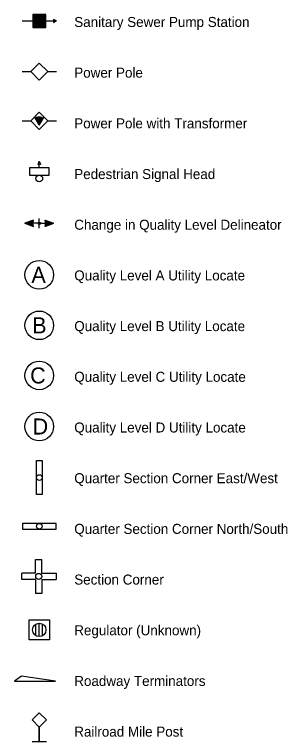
# Model space of a CAD drawing. Extents: x -371 to 730, y -9 to 425.
# Drawn here: x -247.7 to -200.1, y 165.8 to 292.7 of the extents above; entities that cross this region are included whole.
import ezdxf

# ---------------------------------------------------------------- set-up
doc = ezdxf.new("R2010")
doc.units = 0
for name, color, linetype in [('GasReg_ep', 7, 'Continuous'), ('GovQuarterLine_ep', 7, 'Continuous'), ('GovSectionLine_ep', 7, 'Continuous'), ('PedSignal_ep', 7, 'Continuous'), ('PolePower_ep', 7, 'Continuous'), ('RailroadMisc_ep', 7, 'Continuous'), ('SanitaryMisc_ep', 7, 'Continuous'), ('SU_Misc_ep', 7, 'Continuous'), ('SU_QLA_ep', 7, 'Continuous'), ('SU_QLB_ep', 7, 'Continuous'), ('SU_QLC_ep', 7, 'Continuous'), ('SU_QLD_ep', 7, 'Continuous')]:
    doc.layers.add(name, color=color, linetype=linetype)

# ---------------------------------------------------------------- blocks, each defined once
blk = doc.blocks.new('QDEL')
at = {"layer": 'SU_Misc_ep'}
for p, q in [((-1, 0.56), (-2.5, 0)), ((-2.49, 0), (-2.49, 0.01)), ((-2.47, -0.01), (-2.44, 0.02)), ((-2.45, -0.02), (-2.39, 0.04)), ((-2.43, -0.03), (-2.34, 0.06)), ((-2.4, -0.04), (-2.29, 0.08)), ((-2.38, -0.04), (-2.24, 0.1)), ((-2.36, -0.05), (-2.19, 0.12)), ((-2.34, -0.06), (-2.14, 0.13)), ((-2.31, -0.07), (-2.09, 0.15)), ((-2.29, -0.08), (-2.04, 0.17)), ((-2.27, -0.09), (-1.99, 0.19)), ((-2.25, -0.09), (-1.94, 0.21)), ((-2.22, -0.1), (-1.89, 0.23)), ((-2.2, -0.11), (-1.84, 0.25)), ((-2.18, -0.12), (-1.79, 0.26)), ((-2.16, -0.13), (-1.74, 0.28)), ((-2.13, -0.14), (-1.7, 0.3)), ((-2.11, -0.15), (-1.65, 0.32)), ((-2.09, -0.15), (-1.6, 0.34)), ((-2.07, -0.16), (-1.55, 0.36)), ((-2.04, -0.17), (-1.5, 0.37)), ((-2.02, -0.18), (-1.45, 0.39)), ((-2, -0.19), (-1.4, 0.41)), ((-1.98, -0.2), (-1.35, 0.43)), ((-1.95, -0.2), (-1.3, 0.45)), ((-1.93, -0.21), (-1.25, 0.47)), ((-1.91, -0.22), (-1.2, 0.49)), ((-1.89, -0.23), (-1.15, 0.5)), ((-1.86, -0.24), (-1.1, 0.52)), ((-1.84, -0.25), (-1.05, 0.54)), ((-1.82, -0.25), (-1, 0.56)), ((-1.8, -0.26), (-1.01, 0.52)), ((-1.77, -0.27), (-1.02, 0.48)), ((-1.75, -0.28), (-1.03, 0.44)), ((-1.73, -0.29), (-1.04, 0.4)), ((-1.71, -0.3), (-1.05, 0.35)), ((-1.68, -0.31), (-1.07, 0.31)), ((-1.66, -0.31), (-1.08, 0.27)), ((-1.64, -0.32), (-1.09, 0.23)), ((-1.62, -0.33), (-1.1, 0.19)), ((-1.59, -0.34), (-1.11, 0.15)), ((-1.57, -0.35), (-1.12, 0.11)), ((-1.55, -0.36), (-1.13, 0.06)), ((-1.53, -0.36), (-1.14, 0.02)), ((-1.14, 0), (-1, 0.56)), ((0, 0), (0, 0.83)), ((1.14, 0), (1, 0.56)), ((1, 0.56), (2.5, 0)), ((1, 0.56), (1, 0.56)), ((1, -0.56), (1.81, 0.26)), ((1.01, 0.53), (1.03, 0.55)), ((1.01, -0.51), (1.79, 0.26)), ((1.02, 0.51), (1.05, 0.54)), ((1.02, 0.48), (1.07, 0.53)), ((1.02, -0.47), (1.77, 0.27)), ((1.03, 0.46), (1.09, 0.53)), ((1.03, 0.43), (1.12, 0.52)), ((1.03, -0.43), (1.75, 0.28)), ((1.04, 0.41), (1.14, 0.51)), ((1.05, 0.39), (1.16, 0.5)), ((1.05, 0.36), (1.18, 0.49)), ((1.05, -0.39), (1.72, 0.29)), ((1.05, -0.54), (1.84, 0.25)), ((1.06, 0.34), (1.21, 0.48)), ((1.06, -0.35), (1.7, 0.3)), ((1.07, 0.31), (1.23, 0.48)), ((1.07, 0.29), (1.25, 0.47)), ((1.07, -0.31), (1.68, 0.31)), ((1.08, 0.26), (1.27, 0.46)), ((1.08, 0.24), (1.3, 0.45)), ((1.08, -0.26), (1.66, 0.32)), ((1.09, 0.21), (1.32, 0.44)), ((1.09, -0.22), (1.63, 0.32)), ((1.09, -0.53), (1.86, 0.24)), ((1.1, 0.19), (1.34, 0.43)), ((1.1, 0.16), (1.36, 0.42)), ((1.1, -0.18), (1.61, 0.33)), ((1.11, 0.14), (1.39, 0.42)), ((1.11, -0.14), (1.59, 0.34)), ((1.12, 0.11), (1.41, 0.41)), ((1.12, 0.09), (1.43, 0.4)), ((1.12, -0.1), (1.57, 0.35)), ((1.13, 0.06), (1.45, 0.39)), ((1.13, 0.04), (1.48, 0.38)), ((1.13, -0.06), (1.54, 0.36)), ((1.14, -0.02), (1.52, 0.37)), ((1.14, 0.02), (1.5, 0.37)), ((1.14, -0.51), (1.88, 0.23)), ((1.19, -0.49), (1.9, 0.22)), ((1.24, -0.47), (1.93, 0.21)), ((1.29, -0.45), (1.95, 0.21)), ((1.34, -0.43), (1.97, 0.2)), ((1.39, -0.41), (1.99, 0.19)), ((1.44, -0.4), (2.02, 0.18)), ((1.49, -0.38), (2.04, 0.17)), ((1.54, -0.36), (2.06, 0.16)), ((1.59, -0.34), (2.08, 0.16)), ((1.64, -0.32), (2.11, 0.15)), ((1.69, -0.3), (2.13, 0.14)), ((1.74, -0.29), (2.15, 0.13)), ((1.79, -0.27), (2.17, 0.12)), ((1.84, -0.25), (2.2, 0.11)), ((1.89, -0.23), (2.22, 0.1)), ((1.93, -0.21), (2.24, 0.1)), ((1.98, -0.19), (2.27, 0.09)), ((2.03, -0.17), (2.29, 0.08)), ((2.08, -0.16), (2.31, 0.07)), ((2.13, -0.14), (2.33, 0.06)), ((2.18, -0.12), (2.36, 0.05)), ((2.23, -0.1), (2.38, 0.05)), ((2.28, -0.08), (2.4, 0.04)), ((2.33, -0.06), (2.42, 0.03)), ((2.38, -0.05), (2.45, 0.02)), ((2.43, -0.03), (2.47, 0.01)), ((2.48, -0.01), (2.49, 0)), ((0, 0), (-2.5, 0)), ((-2.5, 0), (-1, -0.56)), ((-1.5, -0.37), (-1.14, -0.01)), ((-1.48, -0.38), (-1.14, -0.04)), ((-1.46, -0.39), (-1.13, -0.06)), ((-1.44, -0.4), (-1.12, -0.09)), ((-1.41, -0.41), (-1.12, -0.11)), ((-1.39, -0.41), (-1.11, -0.13)), ((-1.37, -0.42), (-1.1, -0.16)), ((-1.35, -0.43), (-1.1, -0.18)), ((-1.32, -0.44), (-1.09, -0.21)), ((-1.3, -0.45), (-1.09, -0.23)), ((-1.28, -0.46), (-1.08, -0.26)), ((-1.26, -0.47), (-1.07, -0.28)), ((-1.23, -0.47), (-1.07, -0.31)), ((-1.21, -0.48), (-1.06, -0.33)), ((-1.19, -0.49), (-1.05, -0.36)), ((-1.17, -0.5), (-1.05, -0.38)), ((-1, -0.56), (-1.14, 0)), ((-1.14, -0.51), (-1.04, -0.41)), ((-1.12, -0.52), (-1.04, -0.43)), ((-1.1, -0.52), (-1.03, -0.46)), ((-1.08, -0.53), (-1.02, -0.48)), ((-1.05, -0.54), (-1.02, -0.5)), ((-1.03, -0.55), (-1.01, -0.53)), ((-1.01, -0.56), (-1, -0.55)), ((0, -0.83), (0, 0)), ((0, 0), (2.5, 0)), ((2.5, 0), (1, -0.56)), ((1, -0.56), (1.14, 0))]:
    blk.add_line(p, q, dxfattribs=at)
blk.add_circle((0, 0), 0.2, dxfattribs=at)
blk = doc.blocks.new('QLA')
at = {"layer": 'SU_QLA_ep'}
blk.add_circle((0, 0), 2.5, dxfattribs=at)
blk.add_text('A', height=2.8, dxfattribs=at).set_placement((-1.37, -1.4))
blk = doc.blocks.new('QLB')
at = {"layer": 'SU_QLB_ep'}
blk.add_circle((0, 0), 2.5, dxfattribs=at)
blk.add_text('B', height=2.8, dxfattribs=at).set_placement((-1.23, -1.4))
blk = doc.blocks.new('QLC')
at = {"layer": 'SU_QLC_ep'}
blk.add_circle((0, 0), 2.5, dxfattribs=at)
blk.add_text('C', height=2.8, dxfattribs=at).set_placement((-1.59, -1.4))
blk = doc.blocks.new('QLD')
at = {"layer": 'SU_QLD_ep'}
blk.add_circle((0, 0), 2.5, dxfattribs=at)
blk.add_text('D', height=2.8, dxfattribs=at).set_placement((-1.15, -1.4))
blk = doc.blocks.new('roadway_terminators_ArrTermLoc')
blk.add_lwpolyline([(0, 0), (-0.989, 0.148), (-1.187, 0)], close=True)

msp = doc.modelspace()

# ---------------------------------------------------------------- linework, layer by layer
at = {"layer": 'GasReg_ep'}
for p, q in [((-243.95, 184.36), (-243.95, 186.12)), ((-243.37, 184.18), (-243.37, 186.28)), ((-242.78, 184.37), (-242.78, 186.14))]:
    msp.add_line(p, q, dxfattribs=at)
msp.add_lwpolyline([(-241.61, 187), (-241.61, 183.5), (-245.11, 183.5), (-245.11, 187), (-241.61, 187)], dxfattribs=at)
msp.add_circle((-243.37, 185.26), 1.17, dxfattribs=at)
at = {"layer": 'GovQuarterLine_ep'}
for points in [[(-243.86, 208.89), (-243.86, 214.81), (-242.87, 214.81), (-242.87, 208.89)], [(-246.32, 203.83), (-246.32, 202.85), (-240.41, 202.85), (-240.41, 203.83)]]:
    msp.add_lwpolyline(points, close=True, dxfattribs=at)
for centre in [(-243.37, 211.85), (-243.37, 203.34)]:
    msp.add_circle(centre, 0.493, dxfattribs=at)
at = {"layer": 'GovSectionLine_ep'}
for p, q in [((-244, 195.14), (-244, 197.55)), ((-244, 197.55), (-242.95, 197.55)), ((-242.95, 195.14), (-242.95, 197.55)), ((-246.42, 194.07), (-246.42, 195.14)), ((-244, 195.14), (-246.42, 195.14)), ((-242.95, 195.14), (-240.44, 195.14)), ((-240.44, 195.14), (-240.44, 194.07)), ((-244, 194.07), (-246.42, 194.07)), ((-244, 194.07), (-244, 191.64)), ((-242.95, 194.07), (-240.44, 194.07)), ((-242.95, 194.07), (-242.95, 191.64)), ((-242.95, 191.64), (-244, 191.64))]:
    msp.add_line(p, q, dxfattribs=at)
msp.add_circle((-243.47, 194.6), 0.527, dxfattribs=at)
at = {"layer": 'PedSignal_ep'}
msp.add_lwpolyline([(-243.37, 265.91), (-243.37, 266.49), (-243.58, 266.49), (-243.37, 267.07), (-243.15, 266.49), (-243.37, 266.49)], dxfattribs=at)
msp.add_lwpolyline([(-245.1, 264.65), (-241.63, 264.65), (-241.63, 265.91), (-245.1, 265.91)], close=True, dxfattribs=at)
msp.add_circle((-243.37, 264.07), 0.58, dxfattribs=at)
at = {"layer": 'PolePower_ep'}
for p, q in [((-246.37, 282.73), (-244.87, 282.73)), ((-246.37, 282.73), (-244.87, 282.73)), ((-246.37, 282.73), (-244.87, 282.73)), ((-241.87, 282.73), (-240.37, 282.73)), ((-241.87, 282.73), (-240.37, 282.73)), ((-241.87, 282.73), (-240.37, 282.73)), ((-246.37, 274.14), (-244.87, 274.14)), ((-243.37, 273.38), (-244.19, 274.81)), ((-243.37, 273.38), (-244.19, 274.81)), ((-243.37, 273.38), (-244.19, 274.81)), ((-243.37, 273.38), (-244.19, 274.81)), ((-243.37, 273.38), (-243.98, 274.75)), ((-243.37, 273.38), (-243.98, 274.75)), ((-243.37, 273.38), (-243.98, 274.75)), ((-243.37, 273.38), (-243.98, 274.75)), ((-243.37, 273.38), (-243.83, 274.81)), ((-243.37, 273.38), (-243.83, 274.81)), ((-243.37, 273.38), (-243.83, 274.81)), ((-243.37, 273.38), (-243.83, 274.81)), ((-243.37, 273.38), (-243.68, 274.85)), ((-243.37, 273.38), (-243.68, 274.85)), ((-243.37, 273.38), (-243.68, 274.85)), ((-243.37, 273.38), (-243.68, 274.85)), ((-243.37, 273.38), (-243.52, 274.87)), ((-243.37, 273.38), (-243.52, 274.87)), ((-243.37, 273.38), (-243.52, 274.87)), ((-243.37, 273.38), (-243.52, 274.87)), ((-243.37, 273.38), (-243.37, 274.88)), ((-243.37, 273.38), (-243.37, 274.88)), ((-243.37, 273.38), (-243.37, 274.88)), ((-243.37, 273.38), (-243.37, 274.88)), ((-243.37, 273.38), (-243.21, 274.87)), ((-243.37, 273.38), (-243.21, 274.87)), ((-243.37, 273.38), (-243.21, 274.87)), ((-243.37, 273.38), (-243.21, 274.87)), ((-243.37, 273.38), (-243.05, 274.85)), ((-243.37, 273.38), (-243.05, 274.85)), ((-243.37, 273.38), (-243.05, 274.85)), ((-243.37, 273.38), (-243.05, 274.85)), ((-243.37, 273.38), (-242.54, 274.81)), ((-243.37, 273.38), (-242.9, 274.81)), ((-243.37, 273.38), (-242.54, 274.81)), ((-243.37, 273.38), (-242.9, 274.81)), ((-243.37, 273.38), (-242.54, 274.81)), ((-243.37, 273.38), (-242.9, 274.81)), ((-243.37, 273.38), (-242.54, 274.81)), ((-243.37, 273.38), (-242.9, 274.81)), ((-243.37, 273.38), (-242.75, 274.75)), ((-243.37, 273.38), (-242.75, 274.75)), ((-243.37, 273.38), (-242.75, 274.75)), ((-243.37, 273.38), (-242.75, 274.75)), ((-241.87, 274.14), (-240.37, 274.14))]:
    msp.add_line(p, q, dxfattribs=at)
for points in [[(-244.87, 282.73), (-243.37, 281.23), (-241.87, 282.73), (-243.37, 284.23)], [(-244.87, 282.73), (-243.37, 281.23), (-241.87, 282.73), (-243.37, 284.23)], [(-244.87, 282.73), (-243.37, 281.23), (-241.87, 282.73), (-243.37, 284.23)], [(-244.87, 274.14), (-243.37, 272.64), (-241.87, 274.14), (-243.37, 275.64)]]:
    msp.add_lwpolyline(points, close=True, dxfattribs=at)
at = {"layer": 'RailroadMisc_ep'}
msp.add_lwpolyline([(-244.62, 165.78), (-243.37, 165.78), (-243.37, 168.28), (-244.62, 169.53), (-243.37, 170.78), (-242.12, 169.53), (-243.37, 168.28), (-243.37, 165.78), (-242.12, 165.78)], dxfattribs=at)
at = {"layer": 'SanitaryMisc_ep'}
for p, q in [((-244.49, 292.63), (-242.24, 292.63)), ((-244.49, 292.57), (-242.24, 292.57)), ((-244.49, 292.51), (-242.24, 292.51)), ((-244.49, 292.44), (-242.24, 292.44)), ((-244.49, 292.38), (-242.24, 292.38)), ((-244.49, 292.32), (-242.24, 292.32)), ((-244.49, 292.26), (-242.24, 292.26)), ((-244.49, 292.19), (-242.24, 292.19)), ((-244.49, 292.13), (-242.24, 292.13)), ((-244.49, 292.07), (-242.24, 292.07)), ((-244.49, 292.01), (-242.24, 292.01)), ((-244.49, 291.94), (-242.24, 291.94)), ((-246.37, 291.57), (-240.37, 291.57)), ((-244.49, 291.88), (-242.24, 291.88)), ((-244.49, 291.82), (-242.24, 291.82)), ((-244.49, 291.76), (-242.24, 291.76)), ((-244.49, 291.69), (-242.24, 291.69)), ((-244.49, 291.63), (-242.24, 291.63)), ((-244.49, 291.57), (-242.24, 291.57)), ((-244.49, 291.51), (-242.24, 291.51)), ((-244.49, 291.44), (-242.24, 291.44)), ((-244.49, 291.38), (-242.24, 291.38)), ((-244.49, 291.32), (-242.24, 291.32)), ((-244.49, 291.26), (-242.24, 291.26)), ((-244.49, 291.19), (-242.24, 291.19)), ((-244.49, 291.13), (-242.24, 291.13)), ((-244.49, 291.07), (-242.24, 291.07)), ((-244.49, 291.01), (-242.24, 291.01)), ((-244.49, 290.94), (-242.24, 290.94)), ((-244.49, 290.88), (-242.24, 290.88)), ((-244.49, 290.82), (-242.24, 290.82)), ((-244.49, 290.76), (-242.24, 290.76)), ((-244.49, 290.69), (-242.24, 290.69)), ((-244.49, 290.63), (-242.24, 290.63)), ((-244.49, 290.57), (-242.24, 290.57)), ((-244.49, 290.51), (-242.24, 290.51))]:
    msp.add_line(p, q, dxfattribs=at)
msp.add_lwpolyline([(-242.24, 290.44), (-242.24, 292.69), (-244.49, 292.69), (-244.49, 290.44)], close=True, dxfattribs=at)
msp.add_lwpolyline([(-240.87, 291.57), (-240.87, 291.32), (-240.37, 291.57), (-240.87, 291.82), (-240.87, 291.57)], dxfattribs=at)

# ---------------------------------------------------------------- block references
for name, p in [('QDEL', (-243.37, 256.24)), ('QLA', (-243.37, 247.25)), ('QLB', (-243.37, 238.43)), ('QLC', (-243.37, 229.68)), ('QLD', (-243.37, 220.77))]:
    msp.add_blockref(name, p)
at = {"xscale": 6, "yscale": 6}
msp.add_blockref('roadway_terminators_ArrTermLoc', (-240.56, 176.28), dxfattribs=at)

# ---------------------------------------------------------------- texts
for s, p in [('Sanitary Sewer Pump Station', (-237.27, 290.52)), ('Power Pole', (-237.27, 281.67)), ('Power Pole with Transformer', (-237.27, 272.82)), ('Pedestrian Signal Head', (-237.27, 263.97)), ('Change in Quality Level Delineator', (-237.27, 255.12)), ('Quality Level A Utility Locate', (-237.27, 246.27)), ('Quality Level B Utility Locate', (-237.27, 237.42)), ('Quality Level C Utility Locate', (-237.27, 228.57)), ('Quality Level D Utility Locate', (-237.27, 219.72)), ('Quarter Section Corner East/West', (-237.27, 210.87)), ('Quarter Section Corner North/South', (-237.27, 202.02)), ('Section Corner', (-237.27, 193.17)), ('Regulator (Unknown)', (-237.27, 184.32)), ('Roadway Terminators', (-237.27, 175.47)), ('Railroad Mile Post', (-237.27, 166.62))]:
    msp.add_text(s, height=1.75).set_placement(p)

doc.saveas('drawing.dxf')
